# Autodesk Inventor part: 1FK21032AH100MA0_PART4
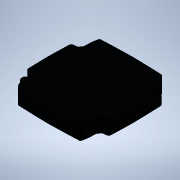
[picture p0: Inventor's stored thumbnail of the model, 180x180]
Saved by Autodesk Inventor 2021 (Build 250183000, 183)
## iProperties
Created: 2025-04
Part Number: 1FK21032AH100MA0_PART4
Material: Generic
Catalog Web Link: www.3dfindit.com
Description: -Servo synchronous motor
Document SubType Name: Modeling
Designer: psAdmin
Mass: 37.514 g
Surface Area: 101.697 cm^2
Volume: 37.514 cm^3
Density: 1 g/cm^3
Appearance: PSOLRGB-38-46-56
Category: PARTsolutions
Title: 1FK21032AH100MA0_PART4
Author: Cadenas PARTsolutions
Comments: Servo synchronous motor
Sending System: PARTsolutions
Preprocessor: ST-DEVELOPER v19.3
PSOL_IDENT_0: {$CADENAS_DATA/23d-libs/siemens_ag/_cat_/12/33/1fk21032ah100ma0.prj},213 {VTYP=3D},{NB=1FK21032AH100
PSOL_IDENT_1: MA0_PART4},{LINA=1FK21032AH100MA0_PART4},{NN=1FK21032AH100MA0_PART4},{NOPRJ=TRUE},{DATE=19.08.2025 1
PSOL_IDENT_2: 4:00:27},{GEOMDATE=30.07.2025 02:02:58},{VERSION=},{LINEID=10},{WBVAR=},{WBNUMERIC=}  {NB=1FK21032AH
PSOL_IDENT_3: 100MA0_PART4},{LINA=1FK21032AH100MA0_PART4},{KT=DUMMY},{PREVIEW=../../../_pool_/d3/78/p_d211_xx_0093
PSOL_IDENT_4: 4j.png},{DESCSHORT=SIMOTICS S-1FK2 HD, SINAMICS S210 3AC 400V-480V, 0.59 Nm, 4500 rpm},{DESCLONG=SIM
PSOL_IDENT_5: OTICS S-1FK2 HD servo motor M0=0.64 Nm; PN = 0.28 kW at nN=4500 rpm (380-480 V); PN = 0.167 kW at nN=
PSOL_IDENT_6: 2500 rpm (200-240 V); with holding brake; degree of protection IP64; cylindrical shaft D14 x 30 mm;
PSOL_IDENT_7: absolute encoder 22-bit + 12-bit multiturn (encoder AM22DQC); with OCC interface; plug size M17, rot
PSOL_IDENT_8: atable; SIMOTICS S-1FK2 servomotorfor a wide range of uses in industrial environments. SIMOTICS S‑1F
PSOL_IDENT_9: K2 servomotors are compact synchronous motors with a high dynamic performance that set themselves ap
PSOL_IDENT_10: art as a result of their high power density, degree of protection and overload capability. The motor
PSOL_IDENT_11: s are available in two variants: as High Dynamic variant (highest dynamic performance as a result of
PSOL_IDENT_12: the low intrinsic moment of inertia for applications demanding a high dynamic performance with low
PSOL_IDENT_13: moved masses) - and as Compact variant (precise and stable closed-loop control for medium up to larg
PSOL_IDENT_14: e moved masses as a result of a medium intrinsic moment of inertia). SIMOTICSS‑1FK2 servomotors full
PSOL_IDENT_15: y exploit their strengths in a system with the SINAMICSS210 frequency converter and simple connectio
PSOL_IDENT_16: n using the one cable connection (OCC). Advantages include the short control and positioning times,
PSOL_IDENT_17: fast and precise correction of disturbing quantities as well as stable control with a high dynamic p
PSOL_IDENT_18: erformance. The servo motors can be configured to address a wide range of requirements. For example
PSOL_IDENT_19: with and without holding brake, IP64 or IP65 degree of protection, singleturn or multiturn absolute
PSOL_IDENT_20: encoders - to name just a few. Further, the servomotors are available in different shaft heights ext
PSOL_IDENT_21: ending from 20 to 100. A shaft sealing ring is available to achieve an IP65 degree of protection and
PSOL_IDENT_22: for subsequent mounting at the motor or as spare part. SIMOTICS - the optimum motor for each and ev
PSOL_IDENT_23: ery motion control application.},{INTNO=195125315563},{SUPPLIERALTNO=1FK2103-2AH10-0MA0},{MANUID=1FK
PSOL_IDENT_24: 21032AH100MA0},{MANUNAME=Siemens},{MANUTYPEDESC=SYNCHRONOUS MOTOR 1FK2 HD 0,64 NM},{AAU732=SIMOTICS}
PSOL_IDENT_25: ,{AAO057=S-1FK2},{AAU734=SIMOTICS S-1FK2 HD servo motor M0=0.64 Nm; PN = 0.28 kW at nN=4500 rpm (380
PSOL_IDENT_26: -480 V); PN = 0.167 kW at nN=2500 rpm (200-240 V); with holding brake; degree of protection IP64; cy
PSOL_IDENT_27: lindrical shaft D14 x 30 mm; absolute encoder 22-bit + 12-bit multiturn (encoder AM22DQC); with OCC
PSOL_IDENT_28: interface; plug size M17, rotatable;},{AAW338=SYNCHRONOUS MOTOR 1FK2 HD 0,64 NM},{AAO742=SIMOTICS},{
PSOL_IDENT_29: AAO663=4034106444723},{NOCUPEROU=1},{PRICEQUANTITY=1},{QUANTITYMIN=1},{QUANTITYINT=1},{CTN=85015100}
PSOL_IDENT_30: ,{COO=RO},{AAO676=1FK2103-2AH10-0MA0},{AAO677=Siemens AG},{ORDERUNIT=C62},{CONTENTUNIT=C62}
NB: 1FK21032AH100MA0_PART4
NT: Servo synchronous motor
NBSYN: $MANUID._PART4
LINA: 1FK21032AH100MA0_PART4
CATALOG: SIEMENS
PREVIEW: ../../../_pool_/d3/78/p_d211_xx_00934j.png
DESCSHORT: SIMOTICS S-1FK2 HD, SINAMICS S210 3AC 400V-480V, 0.59 Nm, 4500 rpm
DESCLONG: SIMOTICS S-1FK2 HD servo motor M0=0.64 Nm; PN = 0.28 kW at nN=4500 rpm (380-480 V); PN = 0.167 kW at nN=2500 rpm (200-240 V); with holding brake; degree of prot
INTNO: 195125315563
SUPPLIERALTNO: 1FK2103-2AH10-0MA0
MANUID: 1FK21032AH100MA0
MANUNAME: Siemens
MANUTYPEDESC: SYNCHRONOUS MOTOR 1FK2 HD 0,64 NM
AAU732: SIMOTICS
AAO057: S-1FK2
AAU734: SIMOTICS S-1FK2 HD servo motor M0=0.64 Nm; PN = 0.28 kW at nN=4500 rpm (380-480 V); PN = 0.167 kW at nN=2500 rpm (200-240 V); with holding brake; degree of prot
AAW338: SYNCHRONOUS MOTOR 1FK2 HD 0,64 NM
AAO742: SIMOTICS
AAO663: 4034106444723.0
NOCUPEROU: 1
PRICEQUANTITY: 1
QUANTITYMIN: 1
QUANTITYINT: 1
CTN: 85015100
COO: RO
ARTICLENO: 1FK21032AH100MA0_PART4
BOMINFO: 1FK21032AH100MA0_PART4
CREATOR: CADENAS GmbH
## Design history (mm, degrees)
feature "2025_04_17_15_06_16_0611"
body "Solid1"
